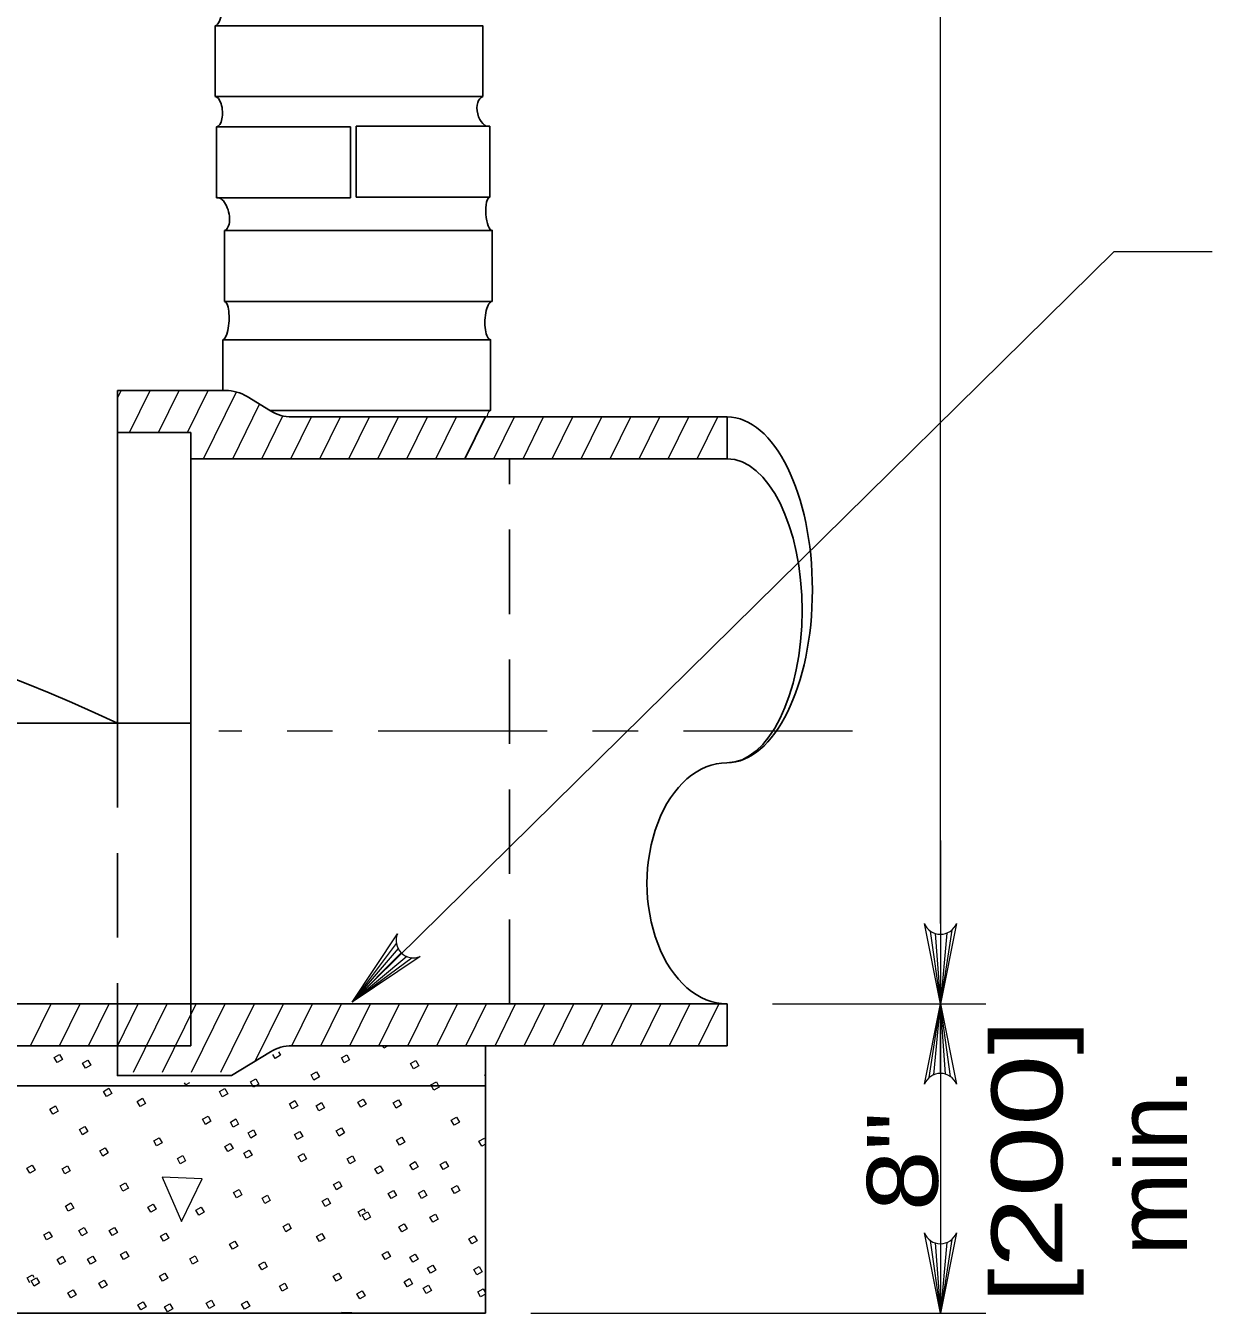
# Model space of a CAD drawing. Extents: x 1083.1 to 1117.1, y 697.4 to 741.4.
# Drawn here: x 1091.69 to 1094.301, y 729.506 to 732.34 of the extents above; entities that cross this region are included whole.
import ezdxf
from ezdxf.enums import TextEntityAlignment as Align

# ---------------------------------------------------------------- set-up
doc = ezdxf.new("R2010")
doc.units = 0
doc.header["$LTSCALE"] = 0.062
doc.linetypes.add('LONG_DASH_SHORT_DASH', pattern=[9.9, 6, -1.2, 1.5, -1.2])
doc.linetypes.add('MEDIUM_DASHED', pattern=[4.5, 3, -1.5])
doc.layers.add('1', color=7, linetype='Continuous', lineweight=13)

msp = doc.modelspace()

# ---------------------------------------------------------------- linework, layer by layer
at = {"layer": '1'}
for p, q in [((1093.70258, 730.36367), (1093.70258, 733.89467)), ((1091.89158, 731.51983), (1091.89983, 731.53667)), ((1091.89158, 731.53667), (1091.89158, 730.80458)), ((1091.89158, 731.51983), (1091.89983, 731.53667)), ((1091.91833, 731.4445), (1091.96375, 731.53667)), ((1091.91833, 731.4445), (1091.96375, 731.53667)), ((1091.98225, 731.4445), (1092.02758, 731.53667)), ((1091.98225, 731.4445), (1092.02758, 731.53667)), ((1092.04608, 731.4445), (1092.0915, 731.53667)), ((1092.04608, 731.4445), (1092.0915, 731.53667)), ((1092.08133, 731.38642), (1092.15375, 731.53342)), ((1092.08133, 731.38642), (1092.15375, 731.53342)), ((1092.14525, 731.38642), (1092.20442, 731.5065)), ((1092.14525, 731.38642), (1092.20442, 731.5065)), ((1092.20908, 731.38642), (1092.25567, 731.48075)), ((1092.20908, 731.38642), (1092.25567, 731.48075)), ((1092.71267, 731.49258), (1092.22725, 731.49258)), ((1092.273, 731.38642), (1092.31842, 731.47858)), ((1092.273, 731.38642), (1092.31842, 731.47858)), ((1092.27542, 731.47858), (1093.23292, 731.47858)), ((1092.33692, 731.38642), (1092.38233, 731.47858)), ((1092.33692, 731.38642), (1092.38233, 731.47858)), ((1092.40075, 731.38642), (1092.44617, 731.47858)), ((1092.40075, 731.38642), (1092.44617, 731.47858)), ((1092.46467, 731.38642), (1092.51008, 731.47858)), ((1092.46467, 731.38642), (1092.51008, 731.47858)), ((1092.52858, 731.38642), (1092.57392, 731.47858)), ((1092.52858, 731.38642), (1092.57392, 731.47858)), ((1092.59242, 731.38642), (1092.63783, 731.47858)), ((1092.59242, 731.38642), (1092.63783, 731.47858)), ((1092.65633, 731.38642), (1092.70175, 731.47858)), ((1092.72017, 731.38642), (1092.76558, 731.47858)), ((1092.72017, 731.38642), (1092.76558, 731.47858)), ((1092.78408, 731.38642), (1092.8295, 731.47858)), ((1092.78408, 731.38642), (1092.8295, 731.47858)), ((1092.848, 731.38642), (1092.89342, 731.47858)), ((1092.848, 731.38642), (1092.89342, 731.47858)), ((1092.91183, 731.38642), (1092.95725, 731.47858)), ((1092.91183, 731.38642), (1092.95725, 731.47858)), ((1092.97575, 731.38642), (1093.02117, 731.47858)), ((1092.97575, 731.38642), (1093.02117, 731.47858)), ((1093.03967, 731.38642), (1093.085, 731.47858)), ((1093.03967, 731.38642), (1093.085, 731.47858)), ((1093.1035, 731.38642), (1093.14892, 731.47858)), ((1093.1035, 731.38642), (1093.14892, 731.47858)), ((1093.16742, 731.38642), (1093.21283, 731.47858)), ((1093.16742, 731.38642), (1093.21283, 731.47858)), ((1091.89158, 731.4445), (1092.05342, 731.4445)), ((1092.05342, 731.38642), (1093.23292, 731.38642)), ((1093.70258, 730.54633), (1093.70258, 730.18667)), ((1093.68017, 730.34692), (1093.70258, 730.18667)), ((1093.72733, 730.34883), (1093.70258, 730.18667)), ((1092.50508, 730.31992), (1092.408, 730.1905)), ((1093.69125, 730.3415), (1093.70258, 730.18667)), ((1093.71692, 730.34267), (1093.70258, 730.18667)), ((1093.70258, 730.33983), (1093.70258, 730.18667)), ((1092.50908, 730.30825), (1092.408, 730.1905)), ((1092.516, 730.29908), (1092.408, 730.1905)), ((1092.52817, 730.29092), (1092.408, 730.1905)), ((1092.53983, 730.288), (1092.408, 730.1905)), ((1091.70033, 730.09458), (1091.74567, 730.18667)), ((1091.76417, 730.09458), (1091.80958, 730.18667)), ((1091.82808, 730.09458), (1091.8735, 730.18667)), ((1091.89158, 730.09383), (1091.93733, 730.18667)), ((1091.92725, 730.0365), (1092.00125, 730.18667)), ((1091.99108, 730.0365), (1092.06508, 730.18667)), ((1092.055, 730.0365), (1092.129, 730.18667)), ((1092.11883, 730.0365), (1092.19292, 730.18667)), ((1092.19467, 730.06067), (1092.25675, 730.18667)), ((1092.27525, 730.09458), (1092.32067, 730.18667)), ((1092.33917, 730.09458), (1092.38458, 730.18667)), ((1092.403, 730.09458), (1092.44842, 730.18667)), ((1092.46692, 730.09458), (1092.51233, 730.18667)), ((1092.53083, 730.09458), (1092.57617, 730.18667)), ((1092.59467, 730.09458), (1092.64008, 730.18667)), ((1092.65858, 730.09458), (1092.704, 730.18667)), ((1092.7225, 730.09458), (1092.76783, 730.18667)), ((1092.78633, 730.09458), (1092.83175, 730.18667)), ((1092.85025, 730.09458), (1092.89567, 730.18667)), ((1092.91408, 730.09458), (1092.9595, 730.18667)), ((1092.978, 730.09458), (1093.02342, 730.18667)), ((1093.08725, 730.18667), (1093.04192, 730.09458)), ((1093.15117, 730.18667), (1093.10575, 730.09458)), ((1093.21508, 730.18667), (1093.16967, 730.09458)), ((1093.33308, 730.18667), (1093.80275, 730.18667)), ((1093.67775, 730.02458), (1093.70258, 730.18667)), ((1093.68817, 730.03067), (1093.70258, 730.18667)), ((1093.70258, 730.0335), (1093.70258, 730.18667)), ((1093.71392, 730.03192), (1093.70258, 730.18667)), ((1093.725, 730.0265), (1093.70258, 730.18667)), ((1093.70258, 730.18667), (1093.70258, 729.50575)), ((1092.70008, 730.03033), (1092.70133, 730.031)), ((1092.70133, 730.02817), (1092.70008, 730.03033)), ((1092.4275, 729.718), (1092.42142, 729.72892)), ((1093.72733, 729.66783), (1093.70258, 729.50575)), ((1093.68017, 729.666), (1093.70258, 729.50575)), ((1093.69125, 729.6605), (1093.70258, 729.50575)), ((1093.71692, 729.66175), (1093.70258, 729.50575)), ((1093.70258, 729.65892), (1093.70258, 729.50575)), ((1091.699, 729.57292), (1091.69292, 729.58375)), ((1092.38475, 729.50767), (1092.38558, 729.50575)), ((1092.43033, 729.50575), (1092.38475, 729.50767)), ((1092.80142, 729.50575), (1093.08067, 729.50575)), ((1092.80142, 729.50575), (1093.80275, 729.50575))]:
    msp.add_line(p, q, dxfattribs=at)
at = {"layer": '1', "lineweight": 25}
for p, q in [((1092.10642, 732.18358), (1092.10642, 732.3395)), ((1092.69558, 732.18358), (1092.10642, 732.18358)), ((1092.40433, 732.117), (1092.10975, 732.117)), ((1092.10975, 731.96108), (1092.10975, 732.117)), ((1092.40433, 731.96108), (1092.40433, 732.117)), ((1092.71133, 732.11833), (1092.41675, 732.11833)), ((1092.41675, 731.96233), (1092.41675, 732.11833)), ((1092.71133, 731.96233), (1092.71133, 732.11833)), ((1092.71133, 731.96233), (1092.41675, 731.96233)), ((1092.40433, 731.96108), (1092.10975, 731.96108)), ((1092.12717, 731.73292), (1092.12717, 731.88892)), ((1092.71642, 731.73292), (1092.12717, 731.73292)), ((1092.12342, 731.53667), (1092.12342, 731.6485)), ((1091.89158, 731.53667), (1091.89158, 730.80458)), ((1091.89158, 731.53667), (1092.12983, 731.53667)), ((1091.89158, 731.53667), (1092.12983, 731.53667)), ((1092.17708, 731.52325), (1092.22825, 731.49192)), ((1092.17708, 731.52325), (1092.22825, 731.49192)), ((1092.71267, 731.49258), (1092.22725, 731.49258)), ((1092.27542, 731.47858), (1093.23292, 731.47858)), ((1092.65633, 731.38642), (1092.70175, 731.47858)), ((1093.23292, 731.38642), (1093.23292, 731.47858)), ((1093.23292, 731.38642), (1093.23292, 731.47858)), ((1091.89158, 731.4445), (1092.05342, 731.4445)), ((1092.05342, 730.09458), (1092.05342, 731.4445)), ((1092.05342, 730.09458), (1092.05342, 731.4445)), ((1092.05342, 731.38642), (1093.23292, 731.38642)), ((1092.05342, 730.80458), (1088.33592, 730.80458)), ((1088.33592, 730.18667), (1093.23292, 730.18667)), ((1093.23292, 730.09458), (1093.23292, 730.18667)), ((1090.446, 730.09458), (1092.05342, 730.09458)), ((1092.27542, 730.09458), (1093.23292, 730.09458)), ((1092.70133, 729.50575), (1092.70133, 730.09458)), ((1092.14283, 730.02892), (1092.22825, 730.08117)), ((1087.74667, 730.00642), (1092.69942, 730.00642)), ((1087.74667, 729.50575), (1092.70133, 729.50575))]:
    msp.add_line(p, q, dxfattribs=at)
at = {"layer": '1', "linetype": 'MEDIUM_DASHED', "lineweight": 25}
for p, q in [((1092.75417, 730.18667), (1092.75417, 731.38642)), ((1091.89158, 730.80458), (1091.89158, 730.09458))]:
    msp.add_line(p, q, dxfattribs=at)
at = {"layer": '1', "linetype": 'MEDIUM_DASHED'}
for p, q in [((1092.75417, 730.18667), (1092.75417, 731.38642)), ((1091.7875, 730.80458), (1091.94933, 730.80458)), ((1091.7875, 730.80458), (1091.94933, 730.80458))]:
    msp.add_line(p, q, dxfattribs=at)
at = {"layer": '1', "linetype": 'LONG_DASH_SHORT_DASH'}
msp.add_line((1093.50925, 730.78658), (1092.11483, 730.78658), dxfattribs=at)
at = {"layer": '1', "lineweight": 25}
for points in [[(1092.69558, 732.18358), (1092.69558, 732.3395), (1092.10642, 732.3395)], [(1092.71642, 731.73292), (1092.71642, 731.88892), (1092.12717, 731.88892)], [(1092.71267, 731.49258), (1092.71267, 731.6485), (1092.12342, 731.6485)], [(1091.89158, 730.09458), (1091.89158, 730.02892), (1092.14283, 730.02892)]]:
    msp.add_lwpolyline(points, dxfattribs=at)
at = {"layer": '1'}
for points in [[(1092.408, 730.1905), (1094.08475, 731.84283), (1094.30058, 731.84283)], [(1093.738, 730.36367), (1093.70258, 730.18667), (1093.66717, 730.36367)], [(1092.55792, 730.291), (1092.408, 730.1905), (1092.50767, 730.34092)], [(1093.66717, 730.00967), (1093.70258, 730.18667), (1093.738, 730.00967)], [(1092.48417, 730.09267), (1092.47808, 730.08917), (1092.47608, 730.09275)], [(1092.24592, 730.08117), (1092.25025, 730.0735), (1092.23842, 730.06675), (1092.2335, 730.0755)], [(1092.0505, 730.01317), (1092.04192, 730.00833), (1092.03933, 730.01292)], [(1092.68708, 729.88458), (1092.699, 729.89133), (1092.70133, 729.88717)], [(1092.70133, 729.87783), (1092.6935, 729.87333), (1092.68708, 729.88458)], [(1092.42142, 729.72892), (1092.43325, 729.73558), (1092.4365, 729.72992)], [(1093.738, 729.68275), (1093.70258, 729.50575), (1093.66717, 729.68275)], [(1091.69292, 729.58375), (1091.70475, 729.5905), (1091.708, 729.58483)], [(1092.6845, 729.55283), (1092.69633, 729.55958), (1092.70133, 729.55075)], [(1092.70133, 729.5475), (1092.69083, 729.54158), (1092.6845, 729.55283)]]:
    msp.add_lwpolyline(points, dxfattribs=at)
for points in [[(1091.75258, 730.06883), (1091.76442, 730.0755), (1091.77075, 730.06433), (1091.75892, 730.05758)], [(1092.38433, 730.06792), (1092.39617, 730.07458), (1092.4025, 730.06342), (1092.39067, 730.05667)], [(1091.815, 730.05633), (1091.82683, 730.06308), (1091.83317, 730.05183), (1091.82133, 730.04517)], [(1092.31775, 730.03025), (1092.32967, 730.03692), (1092.336, 730.02575), (1092.32417, 730.019)], [(1092.53667, 730.05508), (1092.5485, 730.06183), (1092.55483, 730.05058), (1092.543, 730.04392)], [(1092.18442, 730.01475), (1092.19625, 730.0215), (1092.20258, 730.01025), (1092.19075, 730.0035)], [(1092.58158, 730.00825), (1092.5935, 730.01492), (1092.59983, 730.00367), (1092.58792, 729.997)], [(1091.86108, 729.99408), (1091.873, 730.00083), (1091.87933, 729.98958), (1091.8675, 729.98283)], [(1091.935, 729.97217), (1091.94683, 729.97883), (1091.95317, 729.96758), (1091.94133, 729.96092)], [(1092.11608, 729.99358), (1092.12792, 730.00025), (1092.13425, 729.989), (1092.12242, 729.98233)], [(1091.74325, 729.95525), (1091.75508, 729.962), (1091.76142, 729.95075), (1091.74958, 729.944)], [(1092.27008, 729.967), (1092.282, 729.97367), (1092.28833, 729.96242), (1092.2765, 729.95575)], [(1092.32883, 729.96258), (1092.34067, 729.96925), (1092.347, 729.958), (1092.33517, 729.95133)], [(1092.42075, 729.97033), (1092.43258, 729.97708), (1092.43892, 729.96583), (1092.42708, 729.95917)], [(1092.49833, 729.96867), (1092.51017, 729.97542), (1092.5165, 729.96417), (1092.50467, 729.95742)], [(1092.07917, 729.93275), (1092.091, 729.9395), (1092.09733, 729.92825), (1092.0855, 729.9215)], [(1092.14017, 729.92667), (1092.152, 729.93333), (1092.15833, 729.92208), (1092.1465, 729.91542)], [(1092.626, 729.93092), (1092.63783, 729.93767), (1092.64417, 729.92642), (1092.63233, 729.91975)], [(1091.80817, 729.91), (1091.82, 729.91675), (1091.82633, 729.9055), (1091.8145, 729.89875)], [(1092.17908, 729.90258), (1092.19092, 729.90933), (1092.19725, 729.89808), (1092.18542, 729.89133)], [(1092.28117, 729.89933), (1092.293, 729.906), (1092.29933, 729.89475), (1092.2875, 729.88808)], [(1092.37308, 729.90708), (1092.38492, 729.91383), (1092.39125, 729.90258), (1092.37942, 729.89583)], [(1092.50575, 729.88683), (1092.51758, 729.8935), (1092.52392, 729.88225), (1092.51208, 729.87558)], [(1091.85308, 729.86308), (1091.865, 729.86983), (1091.87133, 729.85858), (1091.8595, 729.85183)], [(1091.97158, 729.88525), (1091.98342, 729.89192), (1091.98975, 729.88067), (1091.97792, 729.874)], [(1092.12792, 729.87283), (1092.13975, 729.87958), (1092.14617, 729.86833), (1092.13425, 729.86158)], [(1092.16967, 729.85825), (1092.1815, 729.865), (1092.18783, 729.85375), (1092.176, 729.84708)], [(1092.02358, 729.846), (1092.03542, 729.85275), (1092.04175, 729.8415), (1092.02992, 729.83475)], [(1092.28958, 729.85042), (1092.30142, 729.85717), (1092.30775, 729.84592), (1092.29592, 729.83917)], [(1092.39683, 729.84583), (1092.40875, 729.8525), (1092.41508, 729.84125), (1092.40325, 729.83458)], [(1092.53517, 729.83275), (1092.54708, 729.83942), (1092.55342, 729.82817), (1092.5415, 729.8215)], [(1092.60192, 729.83308), (1092.61375, 729.83975), (1092.62008, 729.8285), (1092.60825, 729.82183)], [(1091.69225, 729.82525), (1091.70408, 729.832), (1091.71042, 729.82075), (1091.69858, 729.814)], [(1091.76983, 729.8235), (1091.78167, 729.83025), (1091.788, 729.819), (1091.77617, 729.81233)], [(1092.45808, 729.82358), (1092.46992, 729.83025), (1092.47625, 729.819), (1092.46442, 729.81233)], [(1091.8975, 729.78583), (1091.90933, 729.79258), (1091.91567, 729.78133), (1091.90383, 729.77458)], [(1091.98983, 729.80525), (1092.03233, 729.70775), (1092.07792, 729.8015)], [(1092.36742, 729.789), (1092.37925, 729.79575), (1092.38558, 729.7845), (1092.37375, 729.77775)], [(1092.627, 729.78042), (1092.63883, 729.78717), (1092.64517, 729.77592), (1092.63333, 729.76917)], [(1092.14742, 729.77125), (1092.15933, 729.778), (1092.16567, 729.76675), (1092.15375, 729.76)], [(1092.20992, 729.75883), (1092.22175, 729.7655), (1092.22808, 729.75425), (1092.21625, 729.74758)], [(1092.34225, 729.75217), (1092.35417, 729.75892), (1092.3605, 729.74767), (1092.34858, 729.74092)], [(1092.4875, 729.7695), (1092.49933, 729.77617), (1092.50575, 729.76492), (1092.49383, 729.75825)], [(1092.55425, 729.76983), (1092.56608, 729.7765), (1092.57242, 729.76525), (1092.56058, 729.75858)], [(1091.77725, 729.74167), (1091.78908, 729.74842), (1091.7955, 729.73717), (1091.78358, 729.73042)], [(1091.95867, 729.7395), (1091.9705, 729.74617), (1091.97683, 729.73492), (1091.965, 729.72825)], [(1092.06442, 729.73275), (1092.07625, 729.7395), (1092.08258, 729.72825), (1092.07075, 729.7215)], [(1092.4305, 729.722), (1092.44233, 729.72875), (1092.44867, 729.7175), (1092.43683, 729.71075)], [(1092.57933, 729.71717), (1092.59117, 729.72392), (1092.5975, 729.71267), (1092.58567, 729.70592)], [(1092.256, 729.6965), (1092.26783, 729.70325), (1092.27417, 729.692), (1092.26233, 729.68525)], [(1092.511, 729.696), (1092.52283, 729.70267), (1092.52917, 729.69142), (1092.51733, 729.68475)], [(1091.72958, 729.67842), (1091.74142, 729.68517), (1091.74783, 729.67392), (1091.73592, 729.66717)], [(1091.80667, 729.68758), (1091.81858, 729.69433), (1091.82492, 729.68308), (1091.81308, 729.67633)], [(1091.87342, 729.68792), (1091.88525, 729.69467), (1091.89158, 729.68342), (1091.87975, 729.67667)], [(1091.98633, 729.6755), (1091.99817, 729.68225), (1092.0045, 729.671), (1091.99267, 729.66425)], [(1092.32992, 729.67458), (1092.34175, 729.68125), (1092.34808, 729.67), (1092.33625, 729.66333)], [(1092.665, 729.66942), (1092.67683, 729.67608), (1092.68317, 729.66492), (1092.67133, 729.65817)], [(1091.8985, 729.63533), (1091.91033, 729.642), (1091.91667, 729.63083), (1091.90483, 729.62408)], [(1092.13808, 729.65767), (1092.15, 729.66442), (1092.15633, 729.65317), (1092.1445, 729.6465)], [(1092.47408, 729.63517), (1092.48592, 729.64192), (1092.49225, 729.63067), (1092.48042, 729.62392)], [(1091.759, 729.62433), (1091.77092, 729.63108), (1091.77725, 729.61983), (1091.76533, 729.61308)], [(1091.82575, 729.62467), (1091.83758, 729.63142), (1091.84392, 729.62017), (1091.83208, 729.61342)], [(1092.05075, 729.62517), (1092.06258, 729.63192), (1092.06892, 729.62067), (1092.05708, 729.614)], [(1092.20308, 729.61242), (1092.21492, 729.61917), (1092.22125, 729.60792), (1092.20942, 729.60117)], [(1092.535, 729.62908), (1092.54683, 729.63575), (1092.55325, 729.6245), (1092.54133, 729.61783)], [(1092.574, 729.605), (1092.58583, 729.61175), (1092.59217, 729.6005), (1092.58033, 729.59383)], [(1091.702, 729.57692), (1091.71383, 729.58358), (1091.72017, 729.57233), (1091.70833, 729.56567)], [(1091.98417, 729.5875), (1091.996, 729.59425), (1092.00233, 729.583), (1091.9905, 729.57625)], [(1092.3665, 729.58767), (1092.37833, 729.59433), (1092.38467, 729.58308), (1092.37283, 729.57642)], [(1092.52283, 729.57525), (1092.53467, 729.582), (1092.541, 729.57075), (1092.52917, 729.564)], [(1092.67608, 729.60175), (1092.68792, 729.60842), (1092.69425, 729.59717), (1092.68242, 729.5905)], [(1091.7825, 729.55083), (1091.79433, 729.55758), (1091.80067, 729.54633), (1091.78883, 729.53958)], [(1091.85083, 729.57208), (1091.86267, 729.57875), (1091.869, 729.5675), (1091.85717, 729.56083)], [(1092.248, 729.5655), (1092.25983, 729.57225), (1092.26617, 729.561), (1092.25433, 729.55425)], [(1092.4185, 729.54842), (1092.43033, 729.55517), (1092.43667, 729.54392), (1092.42483, 729.53717)], [(1092.56458, 729.56075), (1092.57642, 729.56742), (1092.58275, 729.55617), (1092.57092, 729.5495)], [(1091.9365, 729.52425), (1091.94833, 729.531), (1091.95467, 729.51975), (1091.94283, 729.513)], [(1091.99525, 729.51983), (1092.00708, 729.52658), (1092.01342, 729.51533), (1092.00158, 729.50858)], [(1092.08717, 729.52767), (1092.099, 729.53442), (1092.10533, 729.52317), (1092.0935, 729.51642)], [(1092.16475, 729.526), (1092.17658, 729.53267), (1092.18292, 729.52142), (1092.17108, 729.51475)]]:
    msp.add_lwpolyline(points, close=True, dxfattribs=at)
for centre, start, end in [((1093.70252, 730.378), 202.08782, 337.91395), ((1092.54284, 730.32614), 157.243, 293.06912), ((1093.7026, 729.99541), 22.08782, 157.91395), ((1093.70252, 729.69702), 202.08782, 337.91395)]:
    msp.add_arc(centre, 0.0382, start, end, dxfattribs=at)
at = {"layer": '1', "lineweight": 25}
for centre, major_axis, ratio, start_param, end_param in [((1092.10827, 732.38373), (0.00187, 0.0442), 0.320957, 3.1397455, 6.2813381), ((1092.10807, 732.15029), (0.00164, -0.03329), 0.439649, 0.003329, 3.1449217), ((1092.70349, 732.15094), (-0.00739, 0.03275), 0.590174, 0.0247979, 3.1663905), ((1092.11847, 731.92497), (0.0084, -0.03617), 0.496325, 0.0180525, 3.1596452), ((1092.71389, 731.92562), (0.0025, -0.03674), 0.312466, 3.1444636, 6.2860562), ((1092.1253, 731.69073), (-0.00187, -0.0422), 0.283611, 6.2815177, 9.4231104), ((1092.71454, 731.69073), (-0.00186, -0.0422), 0.339712, 3.1395162, 6.2811089), ((1092.12984, 731.4367), (0, 0.09994), 0.944544, 5.7595761, 6.2831856), ((1092.12984, 731.4367), (0, 0.09994), 0.944544, 5.7595761, 6.2831856), ((1092.27545, 731.57851), (0, -0.09994), 0.944544, 5.7595827, 6.2831859), ((1093.23289, 731.09796), (0, -0.3806), 0.493973, 6.2831853, 9.4247779), ((1093.23289, 731.09796), (0, -0.3806), 0.493973, 6.2831853, 9.4247779), ((1093.23289, 731.05189), (0, -0.33452), 0.493973, 6.2831853, 9.4247779), ((1090.22398, 726.80542), (0, 4.37154), 0.944544, 5.8674479, 6.6989234), ((1093.23289, 730.45203), (0, -0.26533), 0.663452, 3.1415925, 6.2831852), ((1093.23289, 730.45203), (0, -0.26533), 0.663452, 3.1415925, 6.2831852), ((1092.27545, 729.99463), (0, 0.09994), 0.944544, 0.0000001, 0.5236033)]:
    msp.add_ellipse(centre, major_axis=major_axis, ratio=ratio, start_param=start_param, end_param=end_param, dxfattribs=at)
at = {"layer": '1'}
for centre, major_axis, ratio, start_param, end_param in [((1092.27545, 731.57851), (0, -0.09994), 0.944544, 5.7595827, 6.2831859), ((1092.71569, 731.45406), (0.00301, -0.03852), 0.313455, 3.1448959, 3.9988386), ((1092.71569, 731.45406), (0.00301, -0.03852), 0.313455, 3.1448959, 3.9988386), ((1093.23289, 731.05189), (0, -0.33452), 0.493973, 6.2831853, 9.4247779)]:
    msp.add_ellipse(centre, major_axis=major_axis, ratio=ratio, start_param=start_param, end_param=end_param, dxfattribs=at)

# ---------------------------------------------------------------- texts
for s, width, p in [('[200]', 1.35, (1093.97083, 729.83975)), ('min.', 1.05, (1094.24483, 729.83975)), ('8"', 1.15, (1093.69683, 729.83975))]:
    msp.add_text(s, height=0.156, rotation=90, dxfattribs=dict(at, width=width)).set_placement(p, align=Align.CENTER)

doc.saveas('drawing.dxf')
